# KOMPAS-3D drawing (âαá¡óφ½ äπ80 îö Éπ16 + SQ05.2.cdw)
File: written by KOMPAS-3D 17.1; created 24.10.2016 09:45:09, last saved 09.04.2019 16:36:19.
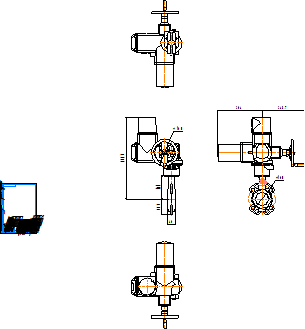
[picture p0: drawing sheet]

Sheet 1: A4, portrait

Title block, sheet 1: name: Гранвэл Ду80 МФ Ру16 + / SQ05.2; material: Внимание! Данный продукт является объектом авторского права ООО «Торговый Дом АДЛ». / Запрещается изменение, копирование, распространение / (в том числе путем копирования на другие сайты и ресурсы в Интернете) / или любое иное использование информации и объектов без предварительного / согласия правообладателя (ООО «Торговый Дом АДЛ»).; mass: 25,6; sheets: 1; organisation: ООО "Торговый дом АДЛ"; sheet format: A4; stored path: \\adlc.lan\data\АДЛ_ПКД\3D-модели\ADL production\Дисковые поворотные затворы ГРАНВЭЛ\межфланцевый с эл.приводом Auma Ру 16\KOMPAS 2D\Гранвэл Ду80 МФ Ру16 + SQ05.2.cdw

Views: Вид 1, Проекционный вид 3, Проекционный вид 4
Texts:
  Klimkovich
  ADL
Dimensions and other numbers on the sheet: 46; 484,5; 160; 93,7; 141; 1:1; 1; 25,6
